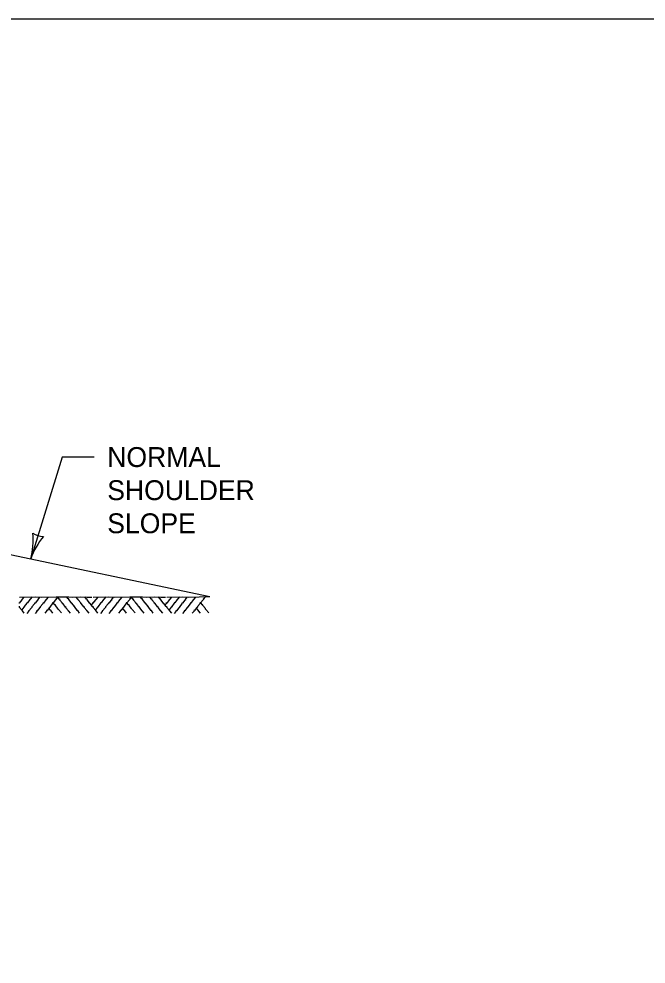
# Model space of a CAD drawing. Extents: x 49991.4 to 50022.1, y 49985 to 50011.4.
# Drawn here: x 50006.771 to 50008.666, y 49996.145 to 49998.999 of the extents above; entities that cross this region are included whole.
import ezdxf

# ---------------------------------------------------------------- set-up
doc = ezdxf.new("R2010")
doc.units = 0
for name, color, linetype in [('Level 1', 7, 'Continuous'), ('Level 2', 7, 'Continuous'), ('Level 3', 7, 'Continuous'), ('Level 4', 7, 'Continuous')]:
    doc.layers.add(name, color=color, linetype=linetype)

msp = doc.modelspace()

# ---------------------------------------------------------------- linework, layer by layer
at = {"layer": 'Level 1'}
msp.add_lwpolyline([(49999.3835, 49998.9992), (50016.7501, 49998.9992), (50016.7501, 49987.7988), (49999.3835, 49987.7988)], close=True, dxfattribs=at)
for points in [[(50006.7866, 49997.2531), (50006.7806, 49997.246), (50006.7814, 49997.2445), (50006.7799, 49997.2445), (50006.7724, 49997.2351), (50006.7715, 49997.2351)], [(50006.7736, 49997.2526), (50006.8206, 49997.2545), (50006.8384, 49997.2526), (50006.884, 49997.2541), (50006.9224, 49997.2543), (50006.933, 49997.2529), (50006.9581, 49997.2545), (50006.9773, 49997.2535), (50006.992, 49997.2526)], [(50006.8112, 49997.2543), (50006.8052, 49997.2471), (50006.806, 49997.2455), (50006.8045, 49997.2455), (50006.7972, 49997.2361), (50006.795, 49997.2361), (50006.7955, 49997.2345), (50006.7877, 49997.2249), (50006.7877, 49997.2229), (50006.786, 49997.2225), (50006.78, 49997.2145)], [(50006.8338, 49997.2525), (50006.8282, 49997.2459), (50006.8288, 49997.2443), (50006.8276, 49997.2443), (50006.8201, 49997.2349), (50006.8182, 49997.2349), (50006.8183, 49997.2331), (50006.8106, 49997.2235), (50006.8106, 49997.2215), (50006.8092, 49997.2211), (50006.8018, 49997.2115), (50006.8, 49997.2115), (50006.8003, 49997.2095), (50006.795, 49997.2033)], [(50006.8594, 49997.2533), (50006.8534, 49997.246), (50006.8542, 49997.2445), (50006.8526, 49997.2445), (50006.8453, 49997.2351), (50006.8432, 49997.2351), (50006.8436, 49997.2333), (50006.836, 49997.2237), (50006.836, 49997.222), (50006.8342, 49997.2213), (50006.827, 49997.2119), (50006.825, 49997.2117), (50006.8255, 49997.21), (50006.8202, 49997.2034)], [(50006.8888, 49997.2541), (50006.8828, 49997.2469), (50006.8836, 49997.2454), (50006.8822, 49997.2454), (50006.8747, 49997.2361), (50006.8729, 49997.2361), (50006.873, 49997.2341), (50006.8654, 49997.2245), (50006.8654, 49997.2229), (50006.8638, 49997.2221), (50006.8564, 49997.2129), (50006.8548, 49997.2125), (50006.855, 49997.2109), (50006.8498, 49997.2045)], [(50006.9272, 49997.2045), (50006.9224, 49997.2107), (50006.9209, 49997.2105), (50006.9212, 49997.2119), (50006.9136, 49997.2211), (50006.9142, 49997.2231), (50006.9122, 49997.2231), (50006.9047, 49997.2329), (50006.903, 49997.2333), (50006.9028, 49997.2349), (50006.8952, 49997.2443), (50006.8956, 49997.246), (50006.8938, 49997.2461), (50006.8886, 49997.2527)], [(50006.9546, 49997.2049), (50006.9491, 49997.2123), (50006.9473, 49997.2119), (50006.9478, 49997.2135), (50006.9402, 49997.2227), (50006.9406, 49997.2245), (50006.9389, 49997.2249), (50006.9312, 49997.2345), (50006.9296, 49997.2347), (50006.9293, 49997.2365), (50006.9218, 49997.2459), (50006.9221, 49997.2477), (50006.9202, 49997.2477), (50006.915, 49997.2543)], [(50006.9833, 49997.2045), (50006.9778, 49997.2115), (50006.9762, 49997.2113), (50006.9766, 49997.2125), (50006.969, 49997.222), (50006.9695, 49997.2239), (50006.9676, 49997.2241), (50006.96, 49997.2335), (50006.9584, 49997.234), (50006.9581, 49997.2359), (50006.9506, 49997.2451), (50006.9509, 49997.2469), (50006.9491, 49997.2469), (50006.944, 49997.2535)], [(50006.9938, 49997.2249), (50006.9868, 49997.2339), (50006.9851, 49997.2341), (50006.9848, 49997.2359), (50006.9772, 49997.2453), (50006.9776, 49997.2471), (50006.9756, 49997.2471), (50006.9702, 49997.2539)], [(50007.0094, 49997.2531), (50007.0034, 49997.246), (50007.0042, 49997.2445), (50007.0026, 49997.2445), (50006.9952, 49997.2351), (50006.9942, 49997.2351)], [(50006.996, 49997.2526), (50007.0433, 49997.2545), (50007.0612, 49997.2526), (50007.1068, 49997.2541), (50007.1452, 49997.2543), (50007.1558, 49997.2529), (50007.1807, 49997.2545), (50007.2, 49997.2535), (50007.2148, 49997.2526)], [(50007.034, 49997.2543), (50007.028, 49997.2471), (50007.0288, 49997.2455), (50007.0272, 49997.2455), (50007.0199, 49997.2361), (50007.0178, 49997.2361), (50007.0182, 49997.2345), (50007.0106, 49997.2249), (50007.0106, 49997.2229), (50007.0088, 49997.2225), (50007.0028, 49997.2145)], [(50007.0565, 49997.2525), (50007.0511, 49997.2459), (50007.0517, 49997.2443), (50007.0502, 49997.2443), (50007.0427, 49997.2349), (50007.0409, 49997.2349), (50007.041, 49997.2331), (50007.0334, 49997.2235), (50007.0334, 49997.2215), (50007.0319, 49997.2211), (50007.0244, 49997.2115), (50007.0228, 49997.2115), (50007.023, 49997.2095), (50007.0178, 49997.2033)], [(50007.0822, 49997.2533), (50007.0762, 49997.246), (50007.0769, 49997.2445), (50007.0754, 49997.2445), (50007.068, 49997.2351), (50007.0661, 49997.2351), (50007.0664, 49997.2333), (50007.0588, 49997.2237), (50007.0588, 49997.222), (50007.0571, 49997.2213), (50007.0498, 49997.2119), (50007.0478, 49997.2117), (50007.0482, 49997.21), (50007.043, 49997.2034)], [(50007.1116, 49997.2541), (50007.1057, 49997.2469), (50007.1063, 49997.2454), (50007.1051, 49997.2454), (50007.0976, 49997.2361), (50007.0956, 49997.2361), (50007.0958, 49997.2341), (50007.0882, 49997.2245), (50007.0882, 49997.2229), (50007.0865, 49997.2221), (50007.0792, 49997.2129), (50007.0775, 49997.2125), (50007.0778, 49997.2109), (50007.0726, 49997.2045)], [(50007.1501, 49997.2045), (50007.1452, 49997.2107), (50007.1436, 49997.2105), (50007.1441, 49997.2119), (50007.1366, 49997.2211), (50007.1369, 49997.2231), (50007.1351, 49997.2231), (50007.1276, 49997.2329), (50007.1256, 49997.2333), (50007.1255, 49997.2349), (50007.118, 49997.2443), (50007.1182, 49997.246), (50007.1165, 49997.2461), (50007.1114, 49997.2527)], [(50007.1774, 49997.2049), (50007.1717, 49997.2123), (50007.17, 49997.2119), (50007.1705, 49997.2135), (50007.163, 49997.2227), (50007.1633, 49997.2245), (50007.1616, 49997.2249), (50007.154, 49997.2345), (50007.1522, 49997.2347), (50007.152, 49997.2365), (50007.1444, 49997.2459), (50007.1447, 49997.2477), (50007.1429, 49997.2477), (50007.1378, 49997.2543)], [(50007.206, 49997.2045), (50007.2005, 49997.2115), (50007.199, 49997.2113), (50007.1993, 49997.2125), (50007.1918, 49997.222), (50007.1922, 49997.2239), (50007.1906, 49997.2241), (50007.1828, 49997.2335), (50007.1812, 49997.234), (50007.1807, 49997.2359), (50007.1732, 49997.2451), (50007.1736, 49997.2469), (50007.1717, 49997.2469), (50007.1668, 49997.2535)], [(50007.2166, 49997.2249), (50007.2095, 49997.2339), (50007.2077, 49997.2341), (50007.2076, 49997.2359), (50007.1999, 49997.2453), (50007.2002, 49997.2471), (50007.1984, 49997.2471), (50007.1932, 49997.2539)], [(50007.2322, 49997.2531), (50007.2262, 49997.246), (50007.2269, 49997.2445), (50007.2254, 49997.2445), (50007.2179, 49997.2351), (50007.217, 49997.2351)], [(50007.2188, 49997.2526), (50007.266, 49997.2545), (50007.2839, 49997.2526), (50007.3483, 49997.2547)], [(50007.2568, 49997.2543), (50007.2508, 49997.2471), (50007.2515, 49997.2455), (50007.25, 49997.2455), (50007.2426, 49997.2361), (50007.2406, 49997.2361), (50007.241, 49997.2345), (50007.2332, 49997.2249), (50007.2332, 49997.2229), (50007.2316, 49997.2225), (50007.2256, 49997.2145)], [(50007.2792, 49997.2525), (50007.2737, 49997.2459), (50007.2746, 49997.2443), (50007.2731, 49997.2443), (50007.2656, 49997.2349), (50007.2636, 49997.2349), (50007.2638, 49997.2331), (50007.2562, 49997.2235), (50007.2562, 49997.2215), (50007.2546, 49997.2211), (50007.2473, 49997.2115), (50007.2455, 49997.2115), (50007.2458, 49997.2095), (50007.2406, 49997.2033)], [(50007.3049, 49997.2533), (50007.2989, 49997.246), (50007.2996, 49997.2445), (50007.2982, 49997.2445), (50007.2906, 49997.2351), (50007.2887, 49997.2351), (50007.2892, 49997.2333), (50007.2815, 49997.2237), (50007.2815, 49997.222), (50007.2797, 49997.2213), (50007.2725, 49997.2119), (50007.2706, 49997.2117), (50007.271, 49997.21), (50007.2658, 49997.2034)], [(50007.3343, 49997.2541), (50007.3286, 49997.2469), (50007.329, 49997.2454), (50007.3277, 49997.2454), (50007.3202, 49997.2361), (50007.3184, 49997.2361), (50007.3186, 49997.2341), (50007.3109, 49997.2245), (50007.3109, 49997.2229), (50007.3092, 49997.2221), (50007.302, 49997.2129), (50007.3002, 49997.2125), (50007.3006, 49997.2109), (50007.2953, 49997.2045)], [(50006.7876, 49997.2046), (50006.7822, 49997.2117), (50006.7805, 49997.2113), (50006.7808, 49997.2129), (50006.7733, 49997.2221), (50006.7738, 49997.2241), (50006.7721, 49997.2243), (50006.7715, 49997.2249)], [(50006.8742, 49997.2047), (50006.8687, 49997.2115), (50006.869, 49997.2131), (50006.867, 49997.2135), (50006.8621, 49997.2199)], [(50006.8998, 49997.2053), (50006.891, 49997.2161), (50006.8894, 49997.2166), (50006.8892, 49997.2184), (50006.8818, 49997.2275), (50006.8819, 49997.2295), (50006.8801, 49997.2295), (50006.875, 49997.2359)], [(50006.9941, 49997.2351), (50006.993, 49997.2351), (50006.9935, 49997.2333), (50006.9905, 49997.2297)], [(50007.0103, 49997.2046), (50007.0049, 49997.2117), (50007.0034, 49997.2113), (50007.0036, 49997.2129), (50006.996, 49997.2221), (50006.9965, 49997.2241), (50006.9947, 49997.2243), (50006.9942, 49997.2249)], [(50007.0967, 49997.2047), (50007.0916, 49997.2115), (50007.0918, 49997.2131), (50007.0898, 49997.2135), (50007.0847, 49997.2199)], [(50007.1225, 49997.2053), (50007.1138, 49997.2161), (50007.1122, 49997.2166), (50007.112, 49997.2184), (50007.1045, 49997.2275), (50007.1046, 49997.2295), (50007.1027, 49997.2295), (50007.0979, 49997.2359)], [(50007.2167, 49997.2351), (50007.2158, 49997.2351), (50007.2162, 49997.2333), (50007.2132, 49997.2297)], [(50007.233, 49997.2046), (50007.2276, 49997.2117), (50007.2262, 49997.2113), (50007.2263, 49997.2129), (50007.2188, 49997.2221), (50007.2192, 49997.2241), (50007.2176, 49997.2243), (50007.217, 49997.2249)], [(50007.3196, 49997.2047), (50007.3142, 49997.2115), (50007.3145, 49997.2131), (50007.3127, 49997.2135), (50007.3076, 49997.2199)], [(50007.3452, 49997.2053), (50007.3366, 49997.2161), (50007.3349, 49997.2166), (50007.3348, 49997.2184), (50007.3272, 49997.2275), (50007.3274, 49997.2295), (50007.3258, 49997.2295), (50007.3206, 49997.2359)]]:
    msp.add_lwpolyline(points, dxfattribs=at)
at = {"layer": 'Level 3'}
for p, q in [((50006.9016, 49997.6761), (50006.8071, 49997.3685)), ((50006.9983, 49997.6761), (50006.9016, 49997.6761))]:
    msp.add_line(p, q, dxfattribs=at)
for centre, radius, start, end in [((50006.5813, 49997.4258), 0.233, 345.7574, 5.0072), ((50007.0168, 49997.2946), 0.2223, 140.3861, 160.5696), ((50006.8448, 49997.4911), 0.0548, 235.0689, 270.7912)]:
    msp.add_arc(centre, radius, start, end, dxfattribs=at)
at = {"layer": 'Level 4'}
msp.add_line((50005.9442, 49997.55), (50007.3483, 49997.2547), dxfattribs=at)

# ---------------------------------------------------------------- texts
at = {"layer": 'Level 2'}
for s, p in [('NORMAL', (50007.0383, 49997.6461)), ('SHOULDER', (50007.0383, 49997.5461)), ('SLOPE', (50007.0383, 49997.4461))]:
    msp.add_text(s, height=0.06, dxfattribs=at).set_placement(p)

doc.saveas('drawing.dxf')
